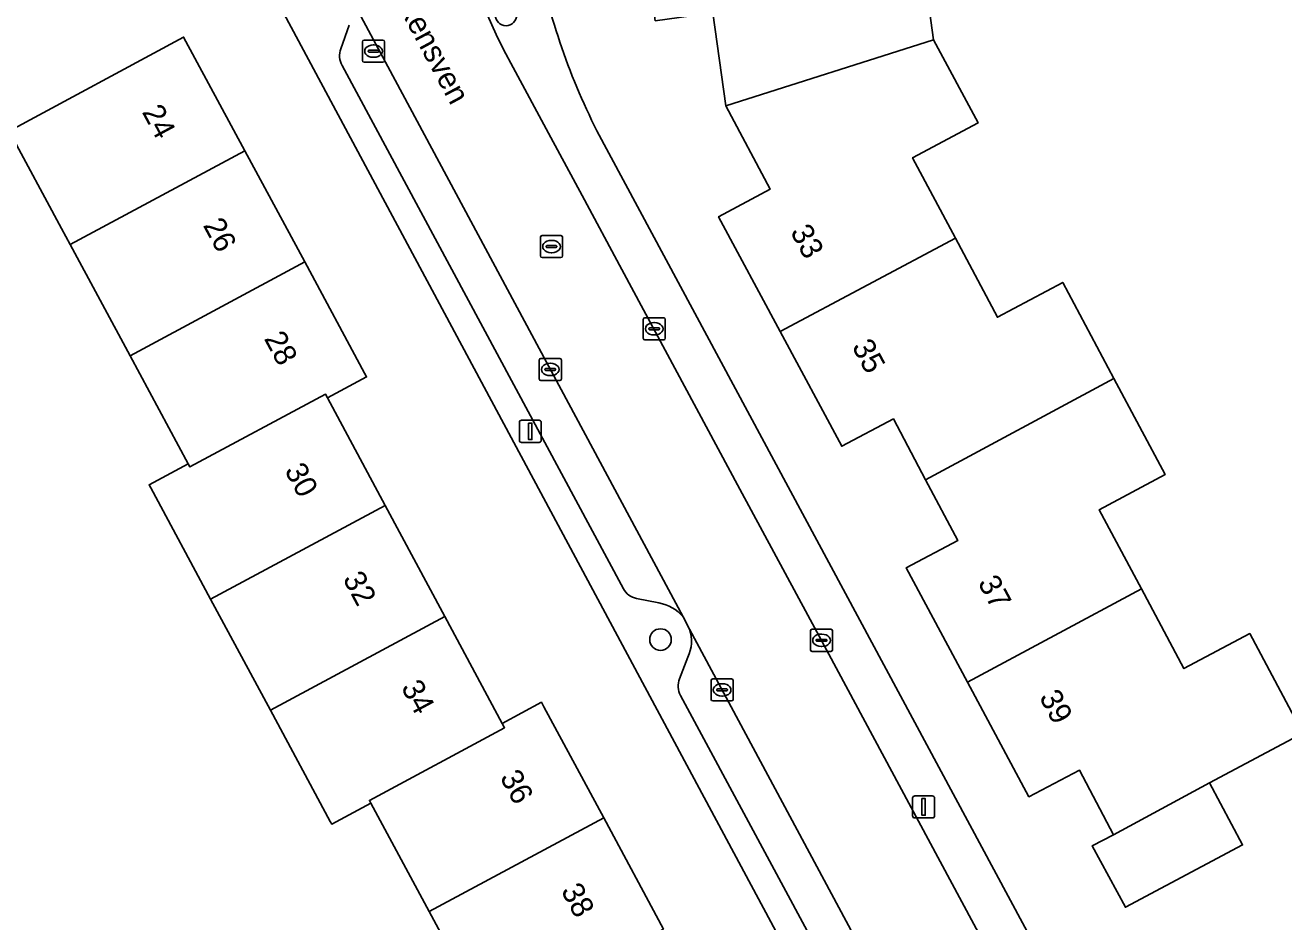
# Model space of a CAD drawing. Extents: x 163426 to 164192, y 380329 to 381641.
# Drawn here: x 163643.5 to 163700.4, y 381156 to 381196.6 of the extents above; entities that cross this region are included whole.
import ezdxf

# ---------------------------------------------------------------- set-up
doc = ezdxf.new("R2010")
doc.units = 0
for name, color, linetype in [('IMGEO_Boom', 7, 'Continuous'), ('IMGEO_Erf', 7, 'Continuous'), ('IMGEO_Kolk', 7, 'Continuous'), ('IMGEO_Lichtmast', 7, 'Continuous'), ('IMGEO_Openbare_ruimte_label', 7, 'Continuous'), ('IMGEO_Pand', 7, 'Continuous'), ('IMGEO_Pand_nummerreeks', 7, 'Continuous'), ('IMGEO_Parkeervlak_open', 7, 'Continuous'), ('IMGEO_Rijbaan_lokaal_open', 7, 'Continuous'), ('IMGEO_Rioolput', 7, 'Continuous'), ('IMGEO_Voetpad_open', 7, 'Continuous')]:
    doc.layers.add(name, color=color, linetype=linetype)

msp = doc.modelspace()

# ---------------------------------------------------------------- linework, layer by layer
at = {"layer": 'IMGEO_Boom'}
for centre in [(163665.247, 381197.073), (163672.239, 381168.797)]:
    msp.add_circle(centre, 0.489, dxfattribs=at)
at = {"layer": 'IMGEO_Erf'}
for points in [[(163684.006, 381200.235), (163684.59, 381195.94), (163686.605, 381192.183), (163683.645, 381190.608), (163685.58, 381186.97), (163687.484, 381183.391), (163690.443, 381184.965), (163692.753, 381180.622), (163695.072, 381176.263), (163692.094, 381174.678), (163694.003, 381171.092), (163695.921, 381167.488), (163698.898, 381169.071), (163701.299, 381164.556), (163697.084, 381162.314), (163698.578, 381159.503), (163693.278, 381156.683), (163691.772, 381159.463), (163692.731, 381159.964), (163691.205, 381162.884), (163688.91, 381161.686), (163686.134, 381166.868), (163683.359, 381172.048), (163685.685, 381173.278), (163684.229, 381176.031), (163682.774, 381178.783), (163680.441, 381177.549), (163677.655, 381182.742), (163674.869, 381187.935), (163677.205, 381189.188), (163675.187, 381192.951), (163674.61, 381197.166)], [(163692.121, 381128.24), (163654.176, 381199.033)], [(163664.48, 381151.456), (163661.773, 381156.488), (163659.132, 381161.396), (163657.363, 381160.443), (163657.295, 381160.569), (163654.588, 381165.602), (163651.88, 381170.634), (163649.173, 381175.665), (163649.097, 381175.807), (163650.865, 381176.759), (163648.234, 381181.648), (163645.527, 381186.679), (163645.133, 381187.411), (163642.764, 381191.813), (163650.656, 381196.072), (163653.429, 381190.921), (163656.138, 381185.89), (163658.847, 381180.859), (163658.938, 381180.69), (163657.169, 381179.738), (163659.78, 381174.874), (163662.483, 381169.839), (163665.078, 381165.005), (163666.847, 381165.958), (163666.956, 381165.756), (163669.667, 381160.726), (163672.378, 381155.696)], [(163669.362, 381191.825), (163689.269, 381154.766), (163691.64, 381154.139), (163699.506, 381139.528), (163698.631, 381137.07), (163700.018, 381134.477)]]:
    msp.add_lwpolyline(points, dxfattribs=at)
msp.add_arc((163696.557, 381205.544), 30.459, 190.4011, 206.7697, dxfattribs=at)
at = {"layer": 'IMGEO_Kolk'}
for p, q in [((163658.753, 381195.007), (163658.753, 381195.859)), ((163658.828, 381195.933), (163659.68, 381195.933)), ((163659.241, 381195.713), (163659.266, 381195.713)), ((163659.754, 381195.859), (163659.754, 381195.007)), ((163659.012, 381195.427), (163659.012, 381195.439)), ((163659.45, 381195.39), (163659.052, 381195.39)), ((163659.055, 381195.476), (163659.453, 381195.476)), ((163659.264, 381195.153), (163659.239, 381195.153)), ((163659.496, 381195.439), (163659.496, 381195.427)), ((163659.68, 381194.933), (163658.828, 381194.933)), ((163671.455, 381182.439), (163671.455, 381183.291)), ((163671.53, 381183.365), (163672.382, 381183.365)), ((163672.456, 381183.291), (163672.456, 381182.439)), ((163671.714, 381182.859), (163671.714, 381182.871)), ((163672.152, 381182.822), (163671.754, 381182.822)), ((163671.757, 381182.908), (163672.155, 381182.908)), ((163671.943, 381183.145), (163671.968, 381183.145)), ((163672.198, 381182.871), (163672.198, 381182.859)), ((163672.382, 381182.365), (163671.53, 381182.365)), ((163671.966, 381182.585), (163671.941, 381182.585)), ((163666.825, 381181.524), (163667.677, 381181.524)), ((163666.75, 381180.598), (163666.75, 381181.45)), ((163667.009, 381181.018), (163667.009, 381181.03)), ((163667.447, 381180.981), (163667.049, 381180.981)), ((163667.052, 381181.067), (163667.45, 381181.067)), ((163667.238, 381181.304), (163667.263, 381181.304)), ((163667.493, 381181.03), (163667.493, 381181.018)), ((163667.751, 381181.45), (163667.751, 381180.598)), ((163667.677, 381180.524), (163666.825, 381180.524)), ((163667.261, 381180.744), (163667.236, 381180.744)), ((163679.024, 381168.339), (163679.024, 381169.191)), ((163679.099, 381169.265), (163679.951, 381169.265)), ((163679.512, 381169.045), (163679.537, 381169.045)), ((163680.025, 381169.191), (163680.025, 381168.339)), ((163679.283, 381168.759), (163679.283, 381168.771)), ((163679.721, 381168.722), (163679.323, 381168.722)), ((163679.326, 381168.808), (163679.724, 381168.808)), ((163679.535, 381168.485), (163679.51, 381168.485)), ((163679.767, 381168.771), (163679.767, 381168.759)), ((163679.951, 381168.265), (163679.099, 381168.265)), ((163674.526, 381166.093), (163674.526, 381166.945)), ((163674.601, 381167.019), (163675.453, 381167.019)), ((163675.014, 381166.799), (163675.039, 381166.799)), ((163675.527, 381166.945), (163675.527, 381166.093)), ((163674.785, 381166.513), (163674.785, 381166.525)), ((163675.223, 381166.476), (163674.825, 381166.476)), ((163674.828, 381166.562), (163675.226, 381166.562)), ((163675.037, 381166.239), (163675.012, 381166.239)), ((163675.269, 381166.525), (163675.269, 381166.513)), ((163675.453, 381166.019), (163674.601, 381166.019))]:
    msp.add_line(p, q, dxfattribs=at)
for points in [[(163658.753, 381195.007), (163658.753, 381195.859)], [(163658.828, 381195.933), (163659.68, 381195.933)], [(163659.754, 381195.859), (163659.754, 381195.007)], [(163659.68, 381194.933), (163658.828, 381194.933)], [(163671.455, 381182.439), (163671.455, 381183.291)], [(163671.53, 381183.365), (163672.382, 381183.365)], [(163672.456, 381183.291), (163672.456, 381182.439)], [(163672.382, 381182.365), (163671.53, 381182.365)], [(163666.825, 381181.524), (163667.677, 381181.524)], [(163666.75, 381180.598), (163666.75, 381181.45)], [(163667.751, 381181.45), (163667.751, 381180.598)], [(163667.677, 381180.524), (163666.825, 381180.524)], [(163679.024, 381168.339), (163679.024, 381169.191)], [(163679.099, 381169.265), (163679.951, 381169.265)], [(163680.025, 381169.191), (163680.025, 381168.339)], [(163679.951, 381168.265), (163679.099, 381168.265)], [(163674.526, 381166.093), (163674.526, 381166.945)], [(163674.601, 381167.019), (163675.453, 381167.019)], [(163675.527, 381166.945), (163675.527, 381166.093)], [(163675.453, 381166.019), (163674.601, 381166.019)]]:
    msp.add_lwpolyline(points, dxfattribs=at)
for centre, radius, start, end in [((163658.83, 381195.857), 0.0765, 91.552, 178.448), ((163658.83, 381195.857), 0.0765, 91.552, 178.448), ((163659.678, 381195.857), 0.0765, 1.552, 88.448), ((163659.678, 381195.857), 0.0765, 1.552, 88.448), ((163659.052, 381195.436), 0.0403, 85.8775, 175.7526), ((163659.049, 381195.426), 0.0366, 178.938, 274.7102), ((163659.453, 381195.433), 0.043, 264.8664, 352.4533), ((163659.457, 381195.438), 0.0386, 1.7309, 96.639), ((163658.83, 381195.009), 0.0765, 181.552, 268.448), ((163658.83, 381195.009), 0.0765, 181.552, 268.448), ((163659.678, 381195.009), 0.0765, 271.552, 358.448), ((163659.678, 381195.009), 0.0765, 271.552, 358.448), ((163671.532, 381183.289), 0.0765, 91.552, 178.448), ((163671.532, 381183.289), 0.0765, 91.552, 178.448), ((163672.38, 381183.289), 0.0765, 1.552, 88.448), ((163672.38, 381183.289), 0.0765, 1.552, 88.448), ((163671.754, 381182.868), 0.0403, 85.8775, 175.7526), ((163671.751, 381182.858), 0.0366, 178.938, 274.7102), ((163672.155, 381182.865), 0.043, 264.8664, 352.4533), ((163672.159, 381182.87), 0.0386, 1.7309, 96.639), ((163671.532, 381182.441), 0.0765, 181.552, 268.448), ((163671.532, 381182.441), 0.0765, 181.552, 268.448), ((163672.38, 381182.441), 0.0765, 271.552, 358.448), ((163672.38, 381182.441), 0.0765, 271.552, 358.448), ((163666.827, 381181.448), 0.0765, 91.552, 178.448), ((163666.827, 381181.448), 0.0765, 91.552, 178.448), ((163667.675, 381181.448), 0.0765, 1.552, 88.448), ((163667.675, 381181.448), 0.0765, 1.552, 88.448), ((163667.049, 381181.027), 0.0403, 85.8775, 175.7526), ((163667.046, 381181.017), 0.0366, 178.938, 274.7102), ((163667.45, 381181.024), 0.043, 264.8664, 352.4533), ((163667.454, 381181.029), 0.0386, 1.7309, 96.639), ((163666.827, 381180.6), 0.0765, 181.552, 268.448), ((163666.827, 381180.6), 0.0765, 181.552, 268.448), ((163667.675, 381180.6), 0.0765, 271.552, 358.448), ((163667.675, 381180.6), 0.0765, 271.552, 358.448), ((163679.101, 381169.189), 0.0765, 91.552, 178.448), ((163679.101, 381169.189), 0.0765, 91.552, 178.448), ((163679.949, 381169.189), 0.0765, 1.552, 88.448), ((163679.949, 381169.189), 0.0765, 1.552, 88.448), ((163679.323, 381168.768), 0.0403, 85.8775, 175.7526), ((163679.32, 381168.758), 0.0366, 178.938, 274.7102), ((163679.724, 381168.765), 0.043, 264.8664, 352.4533), ((163679.728, 381168.77), 0.0386, 1.7309, 96.639), ((163679.101, 381168.341), 0.0765, 181.552, 268.448), ((163679.101, 381168.341), 0.0765, 181.552, 268.448), ((163679.949, 381168.341), 0.0765, 271.552, 358.448), ((163679.949, 381168.341), 0.0765, 271.552, 358.448), ((163674.603, 381166.943), 0.0765, 91.552, 178.448), ((163674.603, 381166.943), 0.0765, 91.552, 178.448), ((163675.451, 381166.943), 0.0765, 1.552, 88.448), ((163675.451, 381166.943), 0.0765, 1.552, 88.448), ((163674.603, 381166.095), 0.0765, 181.552, 268.448), ((163674.603, 381166.095), 0.0765, 181.552, 268.448), ((163674.825, 381166.522), 0.0403, 85.8775, 175.7526), ((163674.822, 381166.512), 0.0366, 178.938, 274.7102), ((163675.226, 381166.519), 0.043, 264.8664, 352.4533), ((163675.23, 381166.524), 0.0386, 1.7309, 96.639), ((163675.451, 381166.095), 0.0765, 271.552, 358.448), ((163675.451, 381166.095), 0.0765, 271.552, 358.448)]:
    msp.add_arc(centre, radius, start, end, dxfattribs=at)
for centre, major_axis, ratio, start_param, end_param in [((163659.24, 381195.433), (-0.387, 0.002), 0.722429, 4.712389, 7.853982), ((163659.265, 381195.433), (-0.39, 0.002), 0.717154, 1.570796, 4.712389), ((163671.942, 381182.865), (-0.387, 0.002), 0.722429, 4.712389, 7.853982), ((163671.967, 381182.865), (-0.39, 0.002), 0.717154, 1.570796, 4.712389), ((163667.237, 381181.024), (-0.387, 0.002), 0.722429, 4.712389, 7.853982), ((163667.262, 381181.024), (-0.39, 0.002), 0.717154, 1.570796, 4.712389), ((163679.511, 381168.765), (-0.387, 0.002), 0.722429, 4.712389, 7.853982), ((163679.536, 381168.765), (-0.39, 0.002), 0.717154, 1.570796, 4.712389), ((163675.013, 381166.519), (-0.387, 0.002), 0.722429, 4.712389, 7.853982), ((163675.038, 381166.519), (-0.39, 0.002), 0.717154, 1.570796, 4.712389)]:
    msp.add_ellipse(centre, major_axis=major_axis, ratio=ratio, start_param=start_param, end_param=end_param, dxfattribs=at)
at = {"layer": 'IMGEO_Lichtmast'}
for p, q in [((163665.851, 381177.825), (163665.851, 381178.625)), ((163665.851, 381178.625), (163665.851, 381177.825)), ((163665.951, 381178.725), (163666.741, 381178.725)), ((163666.741, 381178.725), (163665.951, 381178.725)), ((163666.841, 381178.625), (163666.841, 381177.825)), ((163666.841, 381177.825), (163666.841, 381178.625)), ((163666.741, 381177.725), (163665.951, 381177.725)), ((163665.951, 381177.725), (163666.741, 381177.725)), ((163683.648, 381160.822), (163683.648, 381161.622)), ((163683.648, 381161.622), (163683.648, 381160.822)), ((163683.748, 381161.722), (163684.538, 381161.722)), ((163684.538, 381161.722), (163683.748, 381161.722)), ((163684.638, 381161.622), (163684.638, 381160.822)), ((163684.638, 381160.822), (163684.638, 381161.622)), ((163684.538, 381160.722), (163683.748, 381160.722)), ((163683.748, 381160.722), (163684.538, 381160.722))]:
    msp.add_line(p, q, dxfattribs=at)
for points in [[(163666.271, 381178.6), (163666.421, 381178.6), (163666.421, 381177.85), (163666.271, 381177.85), (163666.271, 381178.6)], [(163684.068, 381161.597), (163684.218, 381161.597), (163684.218, 381160.847), (163684.068, 381160.847), (163684.068, 381161.597)]]:
    msp.add_lwpolyline(points, dxfattribs=at)
for centre, start, end in [((163665.951, 381178.625), 90, 180), ((163665.951, 381178.625), 90, 180), ((163666.741, 381178.625), 0, 90), ((163666.741, 381178.625), 360, 90), ((163665.951, 381177.825), 180, 270), ((163665.951, 381177.825), 180, 270), ((163666.741, 381177.825), 270, 0), ((163666.741, 381177.825), 270, 0), ((163683.748, 381161.622), 90, 180), ((163683.748, 381161.622), 90, 180), ((163684.538, 381161.622), 0, 90), ((163684.538, 381161.622), 360, 90), ((163683.748, 381160.822), 180, 270), ((163683.748, 381160.822), 180, 270), ((163684.538, 381160.822), 270, 0), ((163684.538, 381160.822), 270, 0)]:
    msp.add_arc(centre, 0.1, start, end, dxfattribs=at)
at = {"layer": 'IMGEO_Pand'}
for points in [[(163671.227, 381202.645), (163672.003, 381196.808), (163674.61, 381197.166), (163675.187, 381192.951), (163684.59, 381195.94), (163684.006, 381200.235), (163680.678, 381199.79), (163680.14, 381203.81)], [(163645.527, 381186.679), (163653.429, 381190.921), (163650.656, 381196.072), (163642.764, 381191.813), (163645.133, 381187.411)], [(163684.59, 381195.94), (163675.187, 381192.951), (163677.205, 381189.188), (163674.869, 381187.935), (163677.655, 381182.742), (163685.58, 381186.97), (163683.645, 381190.608), (163686.605, 381192.183)], [(163648.234, 381181.648), (163656.138, 381185.89), (163653.429, 381190.921), (163645.527, 381186.679)], [(163684.229, 381176.031), (163692.753, 381180.622), (163690.443, 381184.965), (163687.484, 381183.391), (163685.58, 381186.97), (163677.655, 381182.742), (163680.441, 381177.549), (163682.774, 381178.783)], [(163658.938, 381180.69), (163658.847, 381180.859), (163656.138, 381185.89), (163648.234, 381181.648), (163650.865, 381176.759), (163650.942, 381176.615), (163657.077, 381179.909), (163657.169, 381179.738)], [(163684.229, 381176.031), (163685.685, 381173.278), (163683.359, 381172.048), (163686.134, 381166.868), (163694.003, 381171.092), (163692.094, 381174.678), (163695.072, 381176.263), (163692.753, 381180.622)], [(163657.169, 381179.738), (163657.077, 381179.909), (163650.942, 381176.615), (163650.865, 381176.759), (163649.097, 381175.807), (163649.173, 381175.665), (163651.88, 381170.634), (163659.78, 381174.874)], [(163659.78, 381174.874), (163651.88, 381170.634), (163654.588, 381165.602), (163662.483, 381169.839)], [(163692.731, 381159.964), (163697.084, 381162.314), (163701.299, 381164.556), (163698.898, 381169.071), (163695.921, 381167.488), (163694.003, 381171.092), (163686.134, 381166.868), (163688.91, 381161.686), (163691.205, 381162.884)], [(163662.483, 381169.839), (163654.588, 381165.602), (163657.295, 381160.569), (163657.363, 381160.443), (163659.132, 381161.396), (163659.066, 381161.52), (163665.185, 381164.805), (163665.078, 381165.005)], [(163666.956, 381165.756), (163666.847, 381165.958), (163665.078, 381165.005), (163665.185, 381164.805), (163659.066, 381161.52), (163659.132, 381161.396), (163661.773, 381156.488), (163669.667, 381160.726)], [(163692.731, 381159.964), (163691.772, 381159.463), (163693.278, 381156.683), (163698.578, 381159.503), (163697.084, 381162.314)], [(163672.378, 381155.696), (163669.667, 381160.726), (163661.773, 381156.488), (163664.48, 381151.456)]]:
    msp.add_lwpolyline(points, close=True, dxfattribs=at)
at = {"layer": 'IMGEO_Parkeervlak_open'}
for points in [[(163673.257, 381169.82), (163658.128, 381198.034)], [(163658.156, 381196.608), (163657.772, 381195.544)], [(163657.829, 381194.781), (163670.557, 381171.096)], [(163671.151, 381170.656), (163672.168, 381170.455)], [(163693.676, 381131.753), (163690.609, 381137.46), (163673.554, 381169.266)], [(163673.481, 381168.003), (163673.098, 381167.024)], [(163673.144, 381166.262), (163680.031, 381153.452), (163681.832, 381150.1), (163691.041, 381132.971)]]:
    msp.add_lwpolyline(points, dxfattribs=at)
for centre, radius, start, end in [((163658.652, 381195.226), 0.936, 160.1458, 208.3989), ((163671.319, 381171.504), 0.864, 208.1567, 258.7856), ((163671.892, 381168.73), 1.747, 38.6069, 80.8998), ((163671.879, 381168.729), 1.759, 335.6146, 17.7695), ((163673.943, 381166.693), 0.908, 158.5894, 208.3199)]:
    msp.add_arc(centre, radius, start, end, dxfattribs=at)
at = {"layer": 'IMGEO_Rijbaan_lokaal_open'}
for points in [[(163648.074, 381274.358), (163648.333, 381272.373), (163651.337, 381250), (163656.063, 381214.795), (163656.199, 381213.848), (163656.365, 381213.282), (163657.589, 381199.034), (163658.128, 381198.034), (163673.257, 381169.82), (163673.554, 381169.266), (163690.609, 381137.46), (163693.676, 381131.753)], [(163698.001, 381134.343), (163696.148, 381137.718), (163687.943, 381153.086), (163684.351, 381159.767), (163679.412, 381168.954), (163675.832, 381175.612), (163670.49, 381185.548), (163668.694, 381188.892), (163667.28, 381191.521), (163665.468, 381194.89)]]:
    msp.add_lwpolyline(points, dxfattribs=at)
msp.add_arc((163686.642, 381206.618), 24.205, 190.6868, 208.9804, dxfattribs=at)
at = {"layer": 'IMGEO_Rioolput'}
for p, q in [((163666.807, 381186.16), (163666.807, 381187.012)), ((163666.882, 381187.086), (163667.734, 381187.086)), ((163667.066, 381186.58), (163667.066, 381186.592)), ((163667.109, 381186.629), (163667.507, 381186.629)), ((163667.295, 381186.866), (163667.32, 381186.866)), ((163667.55, 381186.592), (163667.55, 381186.58)), ((163667.808, 381187.012), (163667.808, 381186.16)), ((163667.734, 381186.086), (163666.882, 381186.086)), ((163667.504, 381186.543), (163667.106, 381186.543)), ((163667.318, 381186.306), (163667.293, 381186.306))]:
    msp.add_line(p, q, dxfattribs=at)
for points in [[(163666.807, 381186.16), (163666.807, 381187.012)], [(163666.882, 381187.086), (163667.734, 381187.086)], [(163667.808, 381187.012), (163667.808, 381186.16)], [(163667.734, 381186.086), (163666.882, 381186.086)]]:
    msp.add_lwpolyline(points, dxfattribs=at)
for centre, radius, start, end in [((163666.884, 381187.01), 0.0765, 91.552, 178.448), ((163666.884, 381187.01), 0.0765, 91.552, 178.448), ((163667.106, 381186.589), 0.0403, 85.8775, 175.7526), ((163667.511, 381186.591), 0.0386, 1.7309, 96.639), ((163667.732, 381187.01), 0.0765, 1.552, 88.448), ((163667.732, 381187.01), 0.0765, 1.552, 88.448), ((163666.884, 381186.162), 0.0765, 181.552, 268.448), ((163666.884, 381186.162), 0.0765, 181.552, 268.448), ((163667.103, 381186.579), 0.0366, 178.938, 274.7102), ((163667.507, 381186.586), 0.043, 264.8664, 352.4533), ((163667.732, 381186.162), 0.0765, 271.552, 358.448), ((163667.732, 381186.162), 0.0765, 271.552, 358.448)]:
    msp.add_arc(centre, radius, start, end, dxfattribs=at)
for centre, major_axis, ratio, start_param, end_param in [((163667.294, 381186.586), (-0.387, 0.002), 0.722429, 4.712389, 7.853982), ((163667.319, 381186.586), (-0.39, 0.002), 0.717154, 1.570796, 4.712389)]:
    msp.add_ellipse(centre, major_axis=major_axis, ratio=ratio, start_param=start_param, end_param=end_param, dxfattribs=at)
at = {"layer": 'IMGEO_Voetpad_open'}
for points in [[(163652.396, 381202.354), (163654.146, 381199.095), (163654.176, 381199.033), (163692.121, 381128.24)], [(163657.772, 381195.544), (163658.156, 381196.608)], [(163670.557, 381171.096), (163657.829, 381194.781)], [(163665.468, 381194.89), (163667.28, 381191.521), (163668.694, 381188.892), (163670.49, 381185.548), (163675.832, 381175.612), (163679.412, 381168.954), (163684.351, 381159.767), (163687.943, 381153.086)], [(163700.018, 381134.477), (163698.631, 381137.07), (163699.506, 381139.528), (163691.64, 381154.139), (163689.269, 381154.766), (163669.362, 381191.825)], [(163672.168, 381170.455), (163671.151, 381170.656)], [(163673.554, 381169.266), (163673.257, 381169.82)], [(163673.098, 381167.024), (163673.481, 381168.003)], [(163691.041, 381132.971), (163681.832, 381150.1), (163680.031, 381153.452), (163673.144, 381166.262)]]:
    msp.add_lwpolyline(points, dxfattribs=at)
for centre, radius, start, end in [((163686.642, 381206.618), 24.205, 190.6868, 208.9804), ((163696.557, 381205.544), 30.459, 190.4011, 206.7697), ((163658.652, 381195.226), 0.936, 160.1458, 208.3989), ((163671.319, 381171.504), 0.864, 208.1567, 258.7856), ((163671.892, 381168.73), 1.747, 38.6069, 80.8998), ((163671.879, 381168.729), 1.759, 335.6146, 17.7695), ((163673.943, 381166.693), 0.908, 158.5894, 208.3199)]:
    msp.add_arc(centre, radius, start, end, dxfattribs=at)

# ---------------------------------------------------------------- texts
at = {"layer": 'IMGEO_Openbare_ruimte_label'}
msp.add_text('Vrijkensven', height=1, rotation=298.2309, dxfattribs=at).set_placement((163659.5, 381199.025))
at = {"layer": 'IMGEO_Pand_nummerreeks'}
for s, rotation, p in [('24', 298.299, (163648.757, 381192.681)), ('26', 298.299, (163651.518, 381187.553)), ('33', 298.2132, (163678.091, 381187.258)), ('28', 298.2982, (163654.279, 381182.424)), ('35', 298.2132, (163680.877, 381182.065)), ('30', 298.2294, (163655.207, 381176.457)), ('32', 298.2279, (163657.841, 381171.551)), ('37', 298.1783, (163686.578, 381171.376)), ('34', 298.2294, (163660.479, 381166.638)), ('39', 298.1783, (163689.354, 381166.195)), ('36', 298.3211, (163664.949, 381162.566)), ('38', 298.3235, (163667.714, 381157.436))]:
    msp.add_text(s, height=1, rotation=rotation, dxfattribs=at).set_placement(p)

doc.saveas('drawing.dxf')
